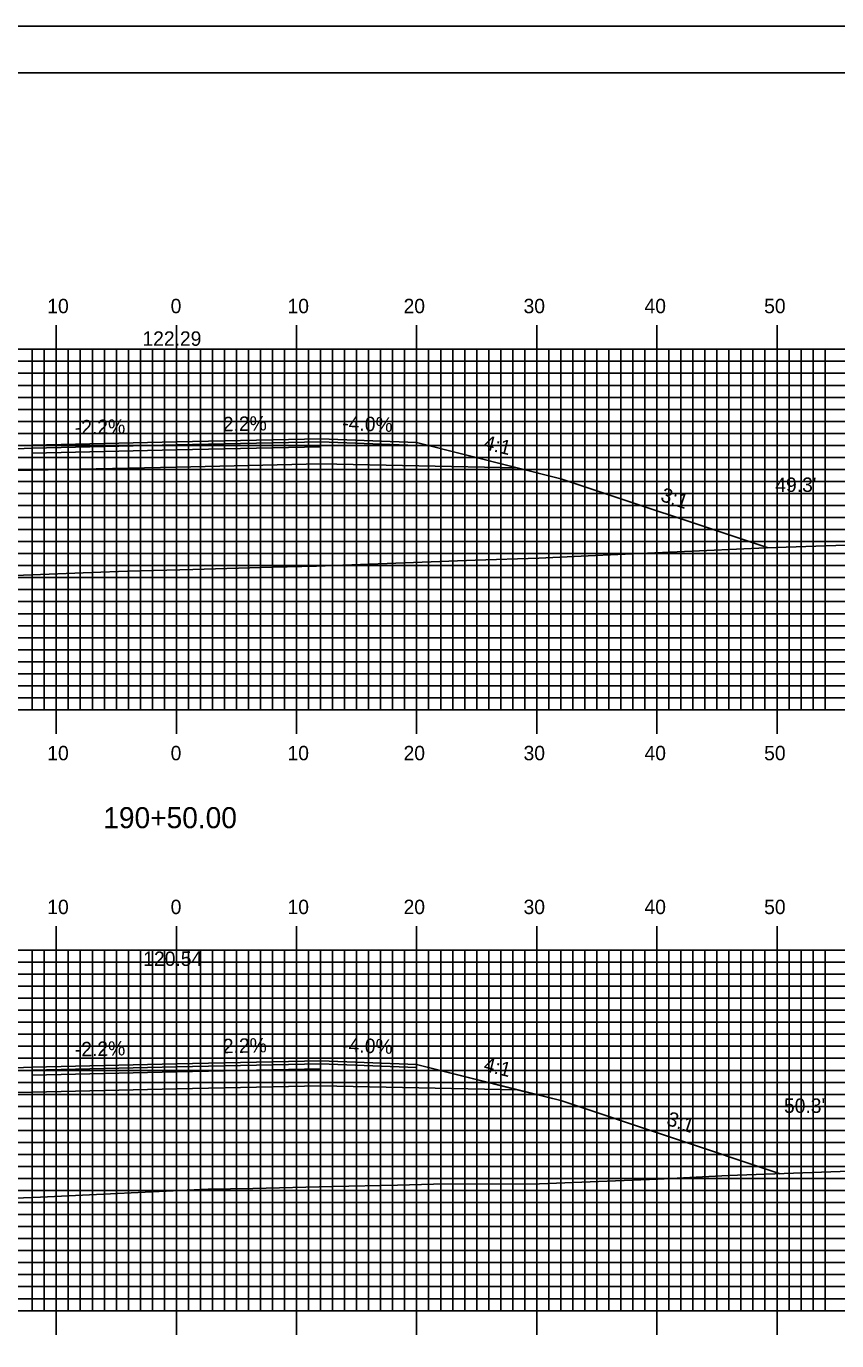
# Model space of a CAD drawing. Extents: x 1788156 to 1788500, y 442591 to 442811.
# Drawn here: x 1788309.6 to 1788377.1, y 442701.2 to 442810.5 of the extents above; entities that cross this region are included whole.
import ezdxf

# ---------------------------------------------------------------- set-up
doc = ezdxf.new("R2010")
doc.units = 0
for name, color, linetype in [('ANNOTATION', 7, 'Continuous'), ('BORDER', 7, 'Continuous'), ('D_Roadway_Centerline', 7, 'Continuous'), ('D_Roadway_Centerline_Text', 7, 'Continuous'), ('D_Roadway_Edge_Shoulder', 7, 'Continuous'), ('D_Roadway_Edge_TW', 7, 'Continuous'), ('D_Roadway_Pavement', 7, 'Continuous'), ('D_Roadway_SlopeLines', 7, 'Continuous'), ('D_Roadway_SubGrade', 7, 'Continuous'), ('D_Text_Standard', 7, 'Continuous'), ('H_V ANNOTATION', 7, 'Continuous'), ('MAJOR', 7, 'Continuous'), ('MINOR', 7, 'Continuous'), ('PLOT BOUNDARY', 7, 'Continuous'), ('S_Roadway_Centerline', 7, 'Continuous')]:
    doc.layers.add(name, color=color, linetype=linetype)

msp = doc.modelspace()

# ---------------------------------------------------------------- linework, layer by layer
at = {"layer": 'BORDER'}
msp.add_lwpolyline([(1788172.53, 442596.67), (1788492.53, 442596.67), (1788492.53, 442806.67), (1788172.53, 442806.67)], close=True, dxfattribs=at)
at = {"layer": 'D_Roadway_Centerline'}
for points in [[(1788263.31, 442763.43), (1788290.13, 442772.37), (1788293.77, 442773.28), (1788302.13, 442775.37), (1788310.13, 442775.69), (1788322.13, 442775.96), (1788334.13, 442776.22), (1788342.13, 442775.9), (1788350.49, 442773.81), (1788354.13, 442772.9), (1788371.39, 442767.15)], [(1788264.21, 442711.98), (1788290.13, 442720.62), (1788293.77, 442721.53), (1788302.13, 442723.62), (1788310.13, 442723.94), (1788322.13, 442724.21), (1788334.13, 442724.47), (1788342.13, 442724.15), (1788350.49, 442722.06), (1788354.13, 442721.15), (1788372.38, 442715.07)]]:
    msp.add_lwpolyline(points, dxfattribs=at)
at = {"layer": 'D_Roadway_Edge_Shoulder'}
for points in [[(1788310.13, 442775.69), (1788302.13, 442775.37), (1788302.13, 442775.12), (1788310.13, 442775.44)], [(1788334.13, 442776.22), (1788342.13, 442775.9), (1788342.13, 442775.65), (1788334.13, 442775.97)], [(1788310.13, 442723.94), (1788302.13, 442723.62), (1788302.13, 442723.37), (1788310.13, 442723.69)], [(1788334.13, 442724.47), (1788342.13, 442724.15), (1788342.13, 442723.9), (1788334.13, 442724.22)]]:
    msp.add_lwpolyline(points, close=True, dxfattribs=at)
at = {"layer": 'D_Roadway_Edge_TW'}
for points in [[(1788310.13, 442775.44), (1788310.13, 442775.69), (1788322.13, 442775.96), (1788334.13, 442776.22), (1788334.13, 442775.97), (1788322.13, 442775.71)], [(1788310.13, 442723.69), (1788310.13, 442723.94), (1788322.13, 442724.21), (1788334.13, 442724.47), (1788334.13, 442724.22), (1788322.13, 442723.96)]]:
    msp.add_lwpolyline(points, close=True, dxfattribs=at)
at = {"layer": 'D_Roadway_Pavement'}
for points in [[(1788310.13, 442775.03), (1788310.13, 442775.44), (1788322.13, 442775.71), (1788334.13, 442775.97), (1788334.13, 442775.55), (1788322.13, 442775.29)], [(1788310.13, 442723.28), (1788310.13, 442723.69), (1788322.13, 442723.96), (1788334.13, 442724.22), (1788334.13, 442723.8), (1788322.13, 442723.54)]]:
    msp.add_lwpolyline(points, close=True, dxfattribs=at)
at = {"layer": 'D_Roadway_SlopeLines'}
for points in [[(1788342.13, 442775.9), (1788354.13, 442772.9), (1788371.39, 442767.15)], [(1788342.13, 442724.15), (1788354.13, 442721.15), (1788372.38, 442715.07)]]:
    msp.add_lwpolyline(points, dxfattribs=at)
at = {"layer": 'D_Roadway_SubGrade'}
for points in [[(1788310.13, 442773.61), (1788293.77, 442773.28), (1788302.13, 442775.37), (1788302.13, 442775.12), (1788310.13, 442775.44), (1788322.13, 442775.71), (1788334.13, 442775.97), (1788342.13, 442775.65), (1788342.13, 442775.9), (1788350.49, 442773.81), (1788334.13, 442774.14), (1788322.13, 442773.87)], [(1788310.13, 442721.86), (1788293.77, 442721.53), (1788302.13, 442723.62), (1788302.13, 442723.37), (1788310.13, 442723.69), (1788322.13, 442723.96), (1788334.13, 442724.22), (1788342.13, 442723.9), (1788342.13, 442724.15), (1788350.49, 442722.06), (1788334.13, 442722.39), (1788322.13, 442722.12)]]:
    msp.add_lwpolyline(points, close=True, dxfattribs=at)
at = {"layer": 'MAJOR'}
for p, q in [((1788312.13, 442785.67), (1788312.13, 442783.67)), ((1788322.13, 442785.67), (1788322.13, 442783.67)), ((1788332.13, 442785.67), (1788332.13, 442783.67)), ((1788342.13, 442785.67), (1788342.13, 442783.67)), ((1788352.13, 442785.67), (1788352.13, 442783.67)), ((1788362.13, 442785.67), (1788362.13, 442783.67)), ((1788372.13, 442785.67), (1788372.13, 442783.67)), ((1788182.13, 442783.67), (1788462.13, 442783.67)), ((1788182.13, 442783.67), (1788462.13, 442783.67)), ((1788312.13, 442753.67), (1788312.13, 442783.67)), ((1788322.13, 442753.67), (1788322.13, 442783.67)), ((1788332.13, 442753.67), (1788332.13, 442783.67)), ((1788342.13, 442753.67), (1788342.13, 442783.67)), ((1788352.13, 442753.67), (1788352.13, 442783.67)), ((1788362.13, 442753.67), (1788362.13, 442783.67)), ((1788372.13, 442753.67), (1788372.13, 442783.67)), ((1788182.13, 442778.67), (1788462.13, 442778.67)), ((1788182.13, 442773.67), (1788462.13, 442773.67)), ((1788182.13, 442768.67), (1788462.13, 442768.67)), ((1788182.13, 442763.67), (1788462.13, 442763.67)), ((1788182.13, 442758.67), (1788462.13, 442758.67)), ((1788182.13, 442753.67), (1788462.13, 442753.67)), ((1788182.13, 442753.67), (1788462.13, 442753.67)), ((1788312.13, 442751.66), (1788312.13, 442753.67)), ((1788322.13, 442751.66), (1788322.13, 442753.67)), ((1788332.13, 442751.66), (1788332.13, 442753.67)), ((1788342.13, 442751.66), (1788342.13, 442753.67)), ((1788352.13, 442751.66), (1788352.13, 442753.67)), ((1788362.13, 442751.66), (1788362.13, 442753.67)), ((1788372.13, 442751.66), (1788372.13, 442753.67)), ((1788312.13, 442735.67), (1788312.13, 442733.67)), ((1788322.13, 442735.67), (1788322.13, 442733.67)), ((1788332.13, 442735.67), (1788332.13, 442733.67)), ((1788342.13, 442735.67), (1788342.13, 442733.67)), ((1788352.13, 442735.67), (1788352.13, 442733.67)), ((1788362.13, 442735.67), (1788362.13, 442733.67)), ((1788372.13, 442735.67), (1788372.13, 442733.67)), ((1788182.13, 442733.67), (1788462.13, 442733.67)), ((1788182.13, 442733.67), (1788462.13, 442733.67)), ((1788312.13, 442703.67), (1788312.13, 442733.67)), ((1788322.13, 442703.67), (1788322.13, 442733.67)), ((1788332.13, 442703.67), (1788332.13, 442733.67)), ((1788342.13, 442703.67), (1788342.13, 442733.67)), ((1788352.13, 442703.67), (1788352.13, 442733.67)), ((1788362.13, 442703.67), (1788362.13, 442733.67)), ((1788372.13, 442703.67), (1788372.13, 442733.67)), ((1788182.13, 442728.67), (1788462.13, 442728.67)), ((1788182.13, 442723.67), (1788462.13, 442723.67)), ((1788182.13, 442718.67), (1788462.13, 442718.67)), ((1788182.13, 442713.67), (1788462.13, 442713.67)), ((1788182.13, 442708.67), (1788462.13, 442708.67)), ((1788182.13, 442703.67), (1788462.13, 442703.67)), ((1788182.13, 442703.67), (1788462.13, 442703.67)), ((1788312.13, 442701.66), (1788312.13, 442703.67)), ((1788322.13, 442701.66), (1788322.13, 442703.67)), ((1788332.13, 442701.66), (1788332.13, 442703.67)), ((1788342.13, 442701.66), (1788342.13, 442703.67)), ((1788352.13, 442701.66), (1788352.13, 442703.67)), ((1788362.13, 442701.66), (1788362.13, 442703.67)), ((1788372.13, 442701.66), (1788372.13, 442703.67))]:
    msp.add_line(p, q, dxfattribs=at)
at = {"layer": 'MINOR'}
for p, q in [((1788310.13, 442753.67), (1788310.13, 442783.67)), ((1788311.13, 442753.67), (1788311.13, 442783.67)), ((1788313.13, 442753.67), (1788313.13, 442783.67)), ((1788314.13, 442753.67), (1788314.13, 442783.67)), ((1788315.13, 442753.67), (1788315.13, 442783.67)), ((1788316.13, 442753.67), (1788316.13, 442783.67)), ((1788317.13, 442753.67), (1788317.13, 442783.67)), ((1788318.13, 442753.67), (1788318.13, 442783.67)), ((1788319.13, 442753.67), (1788319.13, 442783.67)), ((1788320.13, 442753.67), (1788320.13, 442783.67)), ((1788321.13, 442753.67), (1788321.13, 442783.67)), ((1788323.13, 442753.67), (1788323.13, 442783.67)), ((1788324.13, 442753.67), (1788324.13, 442783.67)), ((1788325.13, 442753.67), (1788325.13, 442783.67)), ((1788326.13, 442753.67), (1788326.13, 442783.67)), ((1788327.13, 442753.67), (1788327.13, 442783.67)), ((1788328.13, 442753.67), (1788328.13, 442783.67)), ((1788329.13, 442753.67), (1788329.13, 442783.67)), ((1788330.13, 442753.67), (1788330.13, 442783.67)), ((1788331.13, 442753.67), (1788331.13, 442783.67)), ((1788333.13, 442753.67), (1788333.13, 442783.67)), ((1788334.13, 442753.67), (1788334.13, 442783.67)), ((1788335.13, 442753.67), (1788335.13, 442783.67)), ((1788336.13, 442753.67), (1788336.13, 442783.67)), ((1788337.13, 442753.67), (1788337.13, 442783.67)), ((1788338.13, 442753.67), (1788338.13, 442783.67)), ((1788339.13, 442753.67), (1788339.13, 442783.67)), ((1788340.13, 442753.67), (1788340.13, 442783.67)), ((1788341.13, 442753.67), (1788341.13, 442783.67)), ((1788343.13, 442753.67), (1788343.13, 442783.67)), ((1788344.13, 442753.67), (1788344.13, 442783.67)), ((1788345.13, 442753.67), (1788345.13, 442783.67)), ((1788346.13, 442753.67), (1788346.13, 442783.67)), ((1788347.13, 442753.67), (1788347.13, 442783.67)), ((1788348.13, 442753.67), (1788348.13, 442783.67)), ((1788349.13, 442753.67), (1788349.13, 442783.67)), ((1788350.13, 442753.67), (1788350.13, 442783.67)), ((1788351.13, 442753.67), (1788351.13, 442783.67)), ((1788353.13, 442753.67), (1788353.13, 442783.67)), ((1788354.13, 442753.67), (1788354.13, 442783.67)), ((1788355.13, 442753.67), (1788355.13, 442783.67)), ((1788356.13, 442753.67), (1788356.13, 442783.67)), ((1788357.13, 442753.67), (1788357.13, 442783.67)), ((1788358.13, 442753.67), (1788358.13, 442783.67)), ((1788359.13, 442753.67), (1788359.13, 442783.67)), ((1788360.13, 442753.67), (1788360.13, 442783.67)), ((1788361.13, 442753.67), (1788361.13, 442783.67)), ((1788363.13, 442753.67), (1788363.13, 442783.67)), ((1788364.13, 442753.67), (1788364.13, 442783.67)), ((1788365.13, 442753.67), (1788365.13, 442783.67)), ((1788366.13, 442753.67), (1788366.13, 442783.67)), ((1788367.13, 442753.67), (1788367.13, 442783.67)), ((1788368.13, 442753.67), (1788368.13, 442783.67)), ((1788369.13, 442753.67), (1788369.13, 442783.67)), ((1788370.13, 442753.67), (1788370.13, 442783.67)), ((1788371.13, 442753.67), (1788371.13, 442783.67)), ((1788373.13, 442753.67), (1788373.13, 442783.67)), ((1788374.13, 442753.67), (1788374.13, 442783.67)), ((1788375.13, 442753.67), (1788375.13, 442783.67)), ((1788376.13, 442753.67), (1788376.13, 442783.67)), ((1788182.13, 442782.67), (1788462.13, 442782.67)), ((1788182.13, 442781.67), (1788462.13, 442781.67)), ((1788182.13, 442780.67), (1788462.13, 442780.67)), ((1788182.13, 442779.67), (1788462.13, 442779.67)), ((1788182.13, 442777.67), (1788462.13, 442777.67)), ((1788182.13, 442776.67), (1788462.13, 442776.67)), ((1788182.13, 442775.67), (1788462.13, 442775.67)), ((1788182.13, 442774.67), (1788462.13, 442774.67)), ((1788182.13, 442772.67), (1788462.13, 442772.67)), ((1788182.13, 442771.67), (1788462.13, 442771.67)), ((1788182.13, 442770.67), (1788462.13, 442770.67)), ((1788182.13, 442769.67), (1788462.13, 442769.67)), ((1788182.13, 442767.67), (1788462.13, 442767.67)), ((1788182.13, 442766.67), (1788462.13, 442766.67)), ((1788182.13, 442765.67), (1788462.13, 442765.67)), ((1788182.13, 442764.67), (1788462.13, 442764.67)), ((1788182.13, 442762.67), (1788462.13, 442762.67)), ((1788182.13, 442761.67), (1788462.13, 442761.67)), ((1788182.13, 442760.67), (1788462.13, 442760.67)), ((1788182.13, 442759.67), (1788462.13, 442759.67)), ((1788182.13, 442757.67), (1788462.13, 442757.67)), ((1788182.13, 442756.67), (1788462.13, 442756.67)), ((1788182.13, 442755.67), (1788462.13, 442755.67)), ((1788182.13, 442754.67), (1788462.13, 442754.67)), ((1788310.13, 442703.67), (1788310.13, 442733.67)), ((1788311.13, 442703.67), (1788311.13, 442733.67)), ((1788313.13, 442703.67), (1788313.13, 442733.67)), ((1788314.13, 442703.67), (1788314.13, 442733.67)), ((1788315.13, 442703.67), (1788315.13, 442733.67)), ((1788316.13, 442703.67), (1788316.13, 442733.67)), ((1788317.13, 442703.67), (1788317.13, 442733.67)), ((1788318.13, 442703.67), (1788318.13, 442733.67)), ((1788319.13, 442703.67), (1788319.13, 442733.67)), ((1788320.13, 442703.67), (1788320.13, 442733.67)), ((1788321.13, 442703.67), (1788321.13, 442733.67)), ((1788323.13, 442703.67), (1788323.13, 442733.67)), ((1788324.13, 442703.67), (1788324.13, 442733.67)), ((1788325.13, 442703.67), (1788325.13, 442733.67)), ((1788326.13, 442703.67), (1788326.13, 442733.67)), ((1788327.13, 442703.67), (1788327.13, 442733.67)), ((1788328.13, 442703.67), (1788328.13, 442733.67)), ((1788329.13, 442703.67), (1788329.13, 442733.67)), ((1788330.13, 442703.67), (1788330.13, 442733.67)), ((1788331.13, 442703.67), (1788331.13, 442733.67)), ((1788333.13, 442703.67), (1788333.13, 442733.67)), ((1788334.13, 442703.67), (1788334.13, 442733.67)), ((1788335.13, 442703.67), (1788335.13, 442733.67)), ((1788336.13, 442703.67), (1788336.13, 442733.67)), ((1788337.13, 442703.67), (1788337.13, 442733.67)), ((1788338.13, 442703.67), (1788338.13, 442733.67)), ((1788339.13, 442703.67), (1788339.13, 442733.67)), ((1788340.13, 442703.67), (1788340.13, 442733.67)), ((1788341.13, 442703.67), (1788341.13, 442733.67)), ((1788343.13, 442703.67), (1788343.13, 442733.67)), ((1788344.13, 442703.67), (1788344.13, 442733.67)), ((1788345.13, 442703.67), (1788345.13, 442733.67)), ((1788346.13, 442703.67), (1788346.13, 442733.67)), ((1788347.13, 442703.67), (1788347.13, 442733.67)), ((1788348.13, 442703.67), (1788348.13, 442733.67)), ((1788349.13, 442703.67), (1788349.13, 442733.67)), ((1788350.13, 442703.67), (1788350.13, 442733.67)), ((1788351.13, 442703.67), (1788351.13, 442733.67)), ((1788353.13, 442703.67), (1788353.13, 442733.67)), ((1788354.13, 442703.67), (1788354.13, 442733.67)), ((1788355.13, 442703.67), (1788355.13, 442733.67)), ((1788356.13, 442703.67), (1788356.13, 442733.67)), ((1788357.13, 442703.67), (1788357.13, 442733.67)), ((1788358.13, 442703.67), (1788358.13, 442733.67)), ((1788359.13, 442703.67), (1788359.13, 442733.67)), ((1788360.13, 442703.67), (1788360.13, 442733.67)), ((1788361.13, 442703.67), (1788361.13, 442733.67)), ((1788363.13, 442703.67), (1788363.13, 442733.67)), ((1788364.13, 442703.67), (1788364.13, 442733.67)), ((1788365.13, 442703.67), (1788365.13, 442733.67)), ((1788366.13, 442703.67), (1788366.13, 442733.67)), ((1788367.13, 442703.67), (1788367.13, 442733.67)), ((1788368.13, 442703.67), (1788368.13, 442733.67)), ((1788369.13, 442703.67), (1788369.13, 442733.67)), ((1788370.13, 442703.67), (1788370.13, 442733.67)), ((1788371.13, 442703.67), (1788371.13, 442733.67)), ((1788373.13, 442703.67), (1788373.13, 442733.67)), ((1788374.13, 442703.67), (1788374.13, 442733.67)), ((1788375.13, 442703.67), (1788375.13, 442733.67)), ((1788376.13, 442703.67), (1788376.13, 442733.67)), ((1788182.13, 442732.67), (1788462.13, 442732.67)), ((1788182.13, 442731.67), (1788462.13, 442731.67)), ((1788182.13, 442730.67), (1788462.13, 442730.67)), ((1788182.13, 442729.67), (1788462.13, 442729.67)), ((1788182.13, 442727.67), (1788462.13, 442727.67)), ((1788182.13, 442726.67), (1788462.13, 442726.67)), ((1788182.13, 442725.67), (1788462.13, 442725.67)), ((1788182.13, 442724.67), (1788462.13, 442724.67)), ((1788182.13, 442722.67), (1788462.13, 442722.67)), ((1788182.13, 442721.67), (1788462.13, 442721.67)), ((1788182.13, 442720.67), (1788462.13, 442720.67)), ((1788182.13, 442719.67), (1788462.13, 442719.67)), ((1788182.13, 442717.67), (1788462.13, 442717.67)), ((1788182.13, 442716.67), (1788462.13, 442716.67)), ((1788182.13, 442715.67), (1788462.13, 442715.67)), ((1788182.13, 442714.67), (1788462.13, 442714.67)), ((1788182.13, 442712.67), (1788462.13, 442712.67)), ((1788182.13, 442711.67), (1788462.13, 442711.67)), ((1788182.13, 442710.67), (1788462.13, 442710.67)), ((1788182.13, 442709.67), (1788462.13, 442709.67)), ((1788182.13, 442707.67), (1788462.13, 442707.67)), ((1788182.13, 442706.67), (1788462.13, 442706.67)), ((1788182.13, 442705.67), (1788462.13, 442705.67)), ((1788182.13, 442704.67), (1788462.13, 442704.67))]:
    msp.add_line(p, q, dxfattribs=at)
at = {"layer": 'PLOT BOUNDARY'}
msp.add_lwpolyline([(1788156.34, 442590.55), (1788496.34, 442590.55), (1788496.34, 442810.55), (1788156.34, 442810.55)], close=True, dxfattribs=at)
at = {"layer": 'S_Roadway_Centerline'}
for points in [[(1788258.44, 442763.31), (1788269.72, 442763.6), (1788277.29, 442763.73), (1788282, 442763.84), (1788290.04, 442764.11), (1788296.2, 442764.34), (1788304.41, 442764.68), (1788315.1, 442765.1), (1788318.07, 442765.22), (1788323.51, 442765.34), (1788330.14, 442765.54), (1788333.79, 442765.63), (1788347, 442766.11), (1788352.31, 442766.28), (1788356.42, 442766.47), (1788371.24, 442767.14), (1788390.29, 442767.78)], [(1788248.55, 442711.4), (1788265.85, 442712.05), (1788267.39, 442712.11), (1788267.82, 442712.13), (1788268.62, 442712.13), (1788280.42, 442712.25), (1788286.71, 442712.34), (1788292.1, 442712.51), (1788302, 442712.8), (1788304.47, 442712.87), (1788305.8, 442712.92), (1788310.82, 442713.13), (1788324.76, 442713.79), (1788328.49, 442713.85), (1788335.13, 442714.01), (1788340.54, 442714.11), (1788343.53, 442714.21), (1788352.35, 442714.24), (1788362.21, 442714.61), (1788368.07, 442714.91), (1788381.28, 442715.39)]]:
    msp.add_lwpolyline(points, dxfattribs=at)

# ---------------------------------------------------------------- texts
at = {"layer": 'ANNOTATION'}
for s, rotation, p in [('-2.2%', 1.2603, (1788313.69, 442776.57)), ('2.2%', 1.2603, (1788326.01, 442776.84)), ('-4.0%', 357.7094, (1788335.92, 442776.95)), ('4:1', 345.9638, (1788347.64, 442775.39)), ('3:1', 341.5652, (1788362.36, 442771.07)), ('2.2%', 1.2603, (1788326.01, 442725.09)), ('-4.0%', 357.7094, (1788335.92, 442725.2)), ('-2.2%', 1.2603, (1788313.69, 442724.82)), ('4:1', 345.9638, (1788347.64, 442723.64)), ('3:1', 341.5652, (1788362.86, 442719.15))]:
    msp.add_text(s, height=1.2, rotation=rotation, dxfattribs=at).set_placement(p)
at = {"layer": 'D_Roadway_Centerline'}
for s, p in [('C', (1788322.13, 442775.96)), ('L', (1788322.13, 442775.95)), ('C', (1788322.13, 442724.21)), ('L', (1788322.13, 442724.2))]:
    msp.add_text(s, height=0.0146, dxfattribs=at).set_placement(p)
at = {"layer": 'D_Roadway_Centerline_Text'}
for s, p in [('122.29', (1788319.3, 442783.96)), ('120.54', (1788319.37, 442732.36))]:
    msp.add_text(s, height=1.2, dxfattribs=at).set_placement(p)
at = {"layer": 'D_Text_Standard'}
for s, p in [("49.3'", (1788371.99, 442771.8)), ("50.3'", (1788372.71, 442720.13))]:
    msp.add_text(s, height=1.2, dxfattribs=at).set_placement(p)
at = {"layer": 'H_V ANNOTATION'}
for s, height, p in [('10', 1.2, (1788311.38, 442786.67)), ('0', 1.2, (1788321.65, 442786.67)), ('10', 1.2, (1788331.38, 442786.67)), ('20', 1.2, (1788341.04, 442786.67)), ('30', 1.2, (1788351.03, 442786.67)), ('40', 1.2, (1788361.1, 442786.67)), ('50', 1.2, (1788371.06, 442786.67)), ('10', 1.2, (1788311.38, 442749.47)), ('0', 1.2, (1788321.65, 442749.47)), ('10', 1.2, (1788331.38, 442749.47)), ('20', 1.2, (1788341.04, 442749.47)), ('30', 1.2, (1788351.03, 442749.47)), ('40', 1.2, (1788361.1, 442749.47)), ('50', 1.2, (1788371.06, 442749.47)), ('190+50.00', 1.75, (1788316.04, 442743.82)), ('10', 1.2, (1788311.38, 442736.67)), ('0', 1.2, (1788321.65, 442736.67)), ('10', 1.2, (1788331.38, 442736.67)), ('20', 1.2, (1788341.04, 442736.67)), ('30', 1.2, (1788351.03, 442736.67)), ('40', 1.2, (1788361.1, 442736.67)), ('50', 1.2, (1788371.06, 442736.67))]:
    msp.add_text(s, height=height, dxfattribs=at).set_placement(p)

doc.saveas('drawing.dxf')
